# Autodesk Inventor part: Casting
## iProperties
Created: 2002-02
Part Number: Casting
Document SubType Name: Modeling
Designer: ***
Control State: 0
Master: False
Checked Out: False
Shininess: 77.0
Length Units: 11269
Angle Units: 11279
Time Units: 11290
Mass Units: 11283
Length Display Precision: 3
Angle Display Precision: 2
Density: 0.0
Volumn: 0.0
Area: 0.0
PropertySet Name: Model Information
Author: ***
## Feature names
1. Extrusion1
2. Extrusion2
3. Extrusion3
4. Extrusion4
5. Extrusion5
6. Mirror1
7. Extrusion6
